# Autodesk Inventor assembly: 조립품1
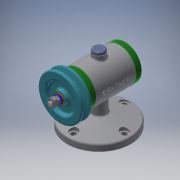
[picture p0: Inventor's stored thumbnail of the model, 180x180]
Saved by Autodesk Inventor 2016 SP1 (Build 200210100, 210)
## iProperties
Created: 2018-12
Part Number: 조립품1
Material: 일반
Document SubType Name: Assembly
Designer: basic
Author: basic
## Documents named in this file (15)
- C:\Users\basic\Desktop\481208V1021\481208V1021\답안조립품.iam
- C:\Users\basic\Desktop\481208V1021\481208V1021\부품1.ipt
- C:\Users\basic\Desktop\481208V1021\481208V1021\베어링 15 x 32 x 9.ipt
- C:\Users\basic\Desktop\481208V1021\481208V1021\축.ipt
- C:\Users\basic\Desktop\481208V1021\481208V1021\앞커버.ipt
- C:\Users\basic\Desktop\481208V1021\481208V1021\뒤커버.ipt
- C:\Users\basic\Desktop\481208V1021\481208V1021\오일 실 15 25 7.ipt
- C:\Users\basic\Desktop\481208V1021\481208V1021\볼트 M4 x 12.ipt
- C:\Users\basic\Desktop\481208V1021\481208V1021\고무캡.ipt
- C:\Users\basic\Desktop\481208V1021\481208V1021\V벨트풀리.ipt
- C:\Users\basic\Desktop\481208V1021\481208V1021\키 3 x 3 x 12.ipt
- C:\Users\basic\Desktop\481208V1021\481208V1021\와셔 8x17.ipt
- C:\Users\basic\Desktop\481208V1021\481208V1021\스프링와셔 8.ipt
- C:\Users\basic\Desktop\481208V1021\481208V1021\너트 M8.ipt
- 너트 M8.ipt
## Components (2 placed, 2 different names)
1. 고무캡:1
2. V벨트풀리:1
